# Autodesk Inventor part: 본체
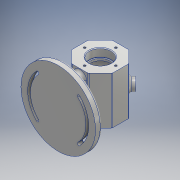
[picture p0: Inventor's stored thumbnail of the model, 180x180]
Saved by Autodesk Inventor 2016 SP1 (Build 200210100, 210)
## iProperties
Created: 2017-06
Part Number: 본체
Material: 알루미늄 6061
Document SubType Name: Modeling
Designer: basic
Density: 2.7 g/cm^3
Appearance: 알루미늄 - 평지
Mass: 554.247 g
Surface Area: 559.738 cm^2
Volume: 205.277 cm^3
Author: basic
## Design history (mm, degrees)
sketch "스케치1"
  geometry: L1 (0, 0)-(30.406, 30.406); L2 (0, 0)-(72.458, 0); L3 (0, 0)-(-65.505, 0); L4 (-30.406, 30.406)-(0, 0); C1 r 55 at (0, 0); A1 r 43 centre (0, 0) between (30.406, -30.406) and (30.406, 30.406); A2 r 48 centre (0, 0) between (33.941, -33.941) and (33.941, 33.941); A3 r 38 centre (0, 0) between (26.87, -26.87) and (26.87, 26.87); A4 r 5 centre (30.406, -30.406) between (26.87, -26.87) and (33.941, -33.941); A5 r 5 centre (30.406, 30.406) between (33.941, 33.941) and (26.87, 26.87); A6 r 43 centre (0, 0) between (-30.406, 30.406) and (-30.406, -30.406); A7 r 48 centre (0, 0) between (-33.941, 33.941) and (-33.941, -33.941); A8 r 38 centre (0, 0) between (-26.87, 26.87) and (-26.87, -26.87); A9 r 5 centre (-30.406, 30.406) between (-26.87, 26.87) and (-33.941, 33.941); A10 r 5 centre (-30.406, -30.406) between (-33.941, -33.941) and (-26.87, -26.87); 3 further points
  constraints: 22 point on circle, 11 centre point, 8 end point, 8 tangent, 3 coincident, 2 horizontal, 2 horizontal alignment
  dimensions: "d0" = 110 diameter of C1; "d1" = 48 radius of A2; "d2" = 48 radius of A7; "d3" = 38 radius of A3; "d4" = 38 radius of A8; "d9" = 45 deg angle of L2 L1; "d10" = 45 deg angle of L3 L4
extrude "돌출1" new body sketch "스케치1" distance "d11" = 10; taper "d12" = 0 deg
sketch "스케치2"
  geometry: L1 (30, 49.574)-(12.426, 32); L2 (12.426, 32)-(-12.426, 32); L3 (-12.426, 32)-(-30, 49.574); L4 (-30, 49.574)-(-30, 74.426); L5 (-30, 74.426)-(-12.426, 92); L6 (-12.426, 92)-(12.426, 92); L7 (12.426, 92)-(30, 74.426); L8 (30, 74.426)-(30, 49.574); L9 (-38, 0)-(-38, 10) reference; L10 (-38, 10)-(38, 10) reference; L11 (38, 10)-(38, 0) reference; L12 (38, 0)-(-38, 0) reference; L13 (55, 10)-(55, 0) reference; L14 (55, 0)-(48, 0) reference; L15 (48, 0)-(48, 10) reference; L16 (48, 10)-(55, 10) reference; L17 (-55, 0)-(-55, 10) reference; L18 (-55, 10)-(-48, 10) reference; L19 (-48, 10)-(-48, 0) reference; L20 (-48, 0)-(-55, 0) reference; C1 r 30 at (0, 62); 2 further points
  constraints: 16 end point, 1 centre point, 1 coincident, 1 parallel, 1 tangent, 1 vertical alignment, 17 other
  dimensions: "d13" = 62 distance from line of L12 point (0, 62); "d14" = 60 diameter of C1
extrude "돌출2" join sketch "스케치2" stored distance "d15" = 70; taper "d16" = 0 deg
sketch "스케치4"
  geometry: L1 (-30, 74.426)-(-30, 49.574) reference; C1 r 16 at (0, 62); 2 further points
  constraints: 1 centre point, 1 horizontal alignment, 1 midpoint, 1 vertical alignment
  dimensions: "d20" = 32 diameter of C1
extrude "돌출3" cut sketch "스케치4" distance "d21" = 12; taper "d22" = 0 deg
sketch "스케치5"
  geometry: L1 (-30, 12.426)-(-30, -12.426) reference; L2 (-12.426, -30)-(12.426, -30) reference; C1 r 14 at (0, 0); 4 further points
  constraints: 3 midpoint, 1 centre point, 1 horizontal alignment, 1 vertical alignment
  dimensions: "d24" = 28 diameter of C1
extrude "돌출4" cut sketch "스케치5" distance "d25" = 3; taper "d26" = 0 deg
sketch "스케치6"
  geometry: L1 (-12.426, 32)-(12.426, 32) reference; L2 (-30, 74.426)-(-30, 49.574) reference; C1 r 16 at (0, 62); 3 further points
  constraints: 2 midpoint, 1 centre point, 1 horizontal alignment, 1 vertical alignment
  dimensions: "d27" = 32 diameter of C1
extrude "돌출5" cut sketch "스케치6" distance "d28" = 12; taper "d29" = 0 deg
sketch "스케치7"
  geometry: L1 (-30, 12.426)-(-30, -12.426) reference; C1 r 14 at (0, 0); 2 further points
  constraints: 1 centre point, 1 horizontal alignment, 1 midpoint, 1 vertical alignment
  dimensions: "d30" = 28 diameter of C1
extrude "돌출6" cut sketch "스케치7" distance "d31" = 3; taper "d32" = 0 deg
node "작업 평면1"
sketch "스케치8"
  geometry: L1 (-38, 0)-(-38, 10) reference; L2 (-38, 10)-(38, 10) reference; L3 (38, 10)-(38, 0) reference; L4 (38, 0)-(-38, 0) reference; L5 (55, 10)-(55, 0) reference; L6 (55, 0)-(48, 0) reference; L7 (48, 0)-(48, 10) reference; L8 (48, 10)-(55, 10) reference; L9 (-55, 0)-(-55, 10) reference; L10 (-55, 10)-(-48, 10) reference; L11 (-48, 10)-(-48, 0) reference; L12 (-48, 0)-(-55, 0) reference; L13 (12.426, 32)-(-12.426, 32) reference; L14 (-12.426, 32)-(-30, 49.574) reference; L15 (-30, 49.574)-(-30, 74.426) reference; L16 (-30, 74.426)-(-12.426, 92) reference; L17 (-12.426, 92)-(12.426, 92) reference; L18 (12.426, 92)-(30, 74.426) reference; L19 (30, 74.426)-(30, 49.574) reference; L20 (30, 49.574)-(12.426, 32) reference; C1 r 25 at (0, 62); 3 further points
  constraints: 2 midpoint, 1 centre point, 1 horizontal alignment, 1 vertical alignment
  dimensions: "d33" = 50 diameter of C1
extrude "돌출7" cut sketch "스케치8" stored distance "d34" = 40; taper "d35" = 0 deg
sketch "스케치9"
  geometry: L1 (0, -24)-(0, 24); L2 (5, -24)-(5, 24); L3 (-5, 24)-(-5, -24); A1 r 5 centre (0, -24) between (-5, -24) and (5, -24); A2 r 5 centre (0, 24) between (5, 24) and (-5, 24); 1 further point
  constraints: 8 end point, 4 point on circle, 4 tangent, 2 centre point, 1 midpoint, 1 parallel, 1 vertical
  dimensions: "d36" = 48 distance of L1.start L1.end; "d37" = 5 radius of A1
extrude "돌출8" join sketch "스케치9" stored distance "d38" = 40; taper "d39" = 0 deg
sketch "스케치10"
  geometry: L1 (-24.853, 70)-(0, 70) reference; C1 r 8 at (-12.426, 35); 2 further points
  constraints: 1 centre point, 1 horizontal alignment, 1 midpoint, 1 vertical alignment
  dimensions: "d40" = 16 diameter of C1
extrude "돌출9" join sketch "스케치10" distance "d41" = 7; taper "d42" = 0 deg
hole "구멍1" diameter "d45" = 8; stored, may be unused: countersink angle "d49" = 90 deg, drill point angle "d51" = 118 deg; dims "d43" = 10, "d44" = 10, "d46" = 6, "d47" = 4, "d48" = 2, "d50" = 8
sketch "스케치11"
  geometry: L1 (-42.426, 10)-(-32.378, 10) reference; L2 (-32.378, 10)-(-32.378, 0) reference; L3 (-32.378, 0)-(-42.426, 0) reference; L4 (-42.426, 0)-(-42.426, 10) reference; L5 (-28.433, 10)-(28.433, 10) reference; L6 (28.433, 10)-(28.433, 0) reference; L7 (28.433, 0)-(-28.433, 0) reference; L8 (-28.433, 0)-(-28.433, 10) reference; L9 (32.378, 10)-(42.426, 10) reference; L10 (42.426, 10)-(42.426, 0) reference; L11 (42.426, 0)-(32.378, 0) reference; L12 (32.378, 0)-(32.378, 10) reference; L13 (-12.426, 92)-(12.426, 92) reference; L14 (12.426, 92)-(30, 74.426) reference; L15 (30, 74.426)-(30, 49.574) reference; L16 (30, 49.574)-(12.426, 32) reference; L17 (12.426, 32)-(-12.426, 32) reference; L18 (-12.426, 32)-(-30, 49.574) reference; L19 (-30, 49.574)-(-30, 74.426) reference; L20 (-30, 74.426)-(-12.426, 92) reference; C1 r 16 at (0, 62) reference; 2 further points
  constraints: 1 vertical alignment
  dimensions: "d52" = 23 distance of C1.centre point (0, 85)
hole "구멍2" sketch "스케치11" at (0, 85) diameter "d53" = 3.242; stored, may be unused: countersink angle "d57" = 90 deg, drill point angle "d59" = 118 deg; dims "d54" = 8, "d55" = 4, "d56" = 2, "d58" = 10
fillet "모깎기1" dims "d63" = 0.3
fillet "모깎기2" dims "d64" = 3
chamfer "모따기1" distance "d65" = 1; stored, may be unused: second distance "d66" = 2, angle "d67" = 45 deg
chamfer "모따기2" distance "d68" = 1; stored, may be unused: second distance "d69" = 2, angle "d70" = 45 deg
fillet "모깎기3" dims "d71" = 5
sketch "스케치13"
  geometry: C1 r 55 at (0, 0) reference; A1 r 5 centre (30.406, 30.406) between (33.941, 33.941) and (26.87, 26.87) reference; A2 r 38 centre (0, 0) between (26.87, -26.87) and (26.87, 26.87) reference; A3 r 5 centre (30.406, -30.406) between (26.87, -26.87) and (33.941, -33.941) reference; A4 r 48 centre (0, 0) between (33.941, -33.941) and (33.941, 33.941) reference; A5 r 5 centre (-30.406, -30.406) between (-33.941, -33.941) and (-26.87, -26.87) reference; A6 r 38 centre (0, 0) between (-26.87, 26.87) and (-26.87, -26.87) reference; A7 r 5 centre (-30.406, 30.406) between (-26.87, 26.87) and (-33.941, 33.941) reference; A8 r 48 centre (0, 0) between (-33.941, 33.941) and (-33.941, -33.941) reference; A9 r 2 centre (30.406, 30.406) between (31.82, 31.82) and (28.991, 28.991); A10 r 45 centre (0, 0) between (31.82, -31.82) and (31.82, 31.82); A11 r 2 centre (30.406, -30.406) between (28.991, -28.991) and (31.82, -31.82); A12 r 41 centre (0, 0) between (28.991, -28.991) and (28.991, 28.991); A13 r 2 centre (-30.406, -30.406) between (-31.82, -31.82) and (-28.991, -28.991); A14 r 45 centre (0, 0) between (-31.82, 31.82) and (-31.82, -31.82); A15 r 2 centre (-30.406, 30.406) between (-28.991, 28.991) and (-31.82, 31.82); A16 r 41 centre (0, 0) between (-28.991, 28.991) and (-28.991, -28.991); 1 further point
  constraints: 16 point on circle, 8 centre point, 6 other
  dimensions: "d88" = 2 radius of A13; "d89" = 2 radius of A9
  node "절단 모서리 투영6"
extrude "돌출10" join sketch "스케치13" distance "d75" = 7; taper "d76" = 0 deg
extrude "돌출11" join sketch "스케치13" distance "d77" = 7; taper "d78" = 0 deg
fillet "모깎기4" dims "d79" = 3
fillet "모깎기5" dims "d80" = 3
chamfer "모따기3" distance "d81" = 1; stored, may be unused: second distance "d82" = 2, angle "d83" = 45 deg
sketch "스케치14"
  geometry: L1 (22.853, 0)-(0, 0) reference; L2 (-18.574, 70)-(-18.574, 0) reference; 2 further points
  constraints: 1 other
  dimensions: "d84" = 35 distance from line of L1 point (11.426, 35); "d85" = 30 distance from line of L2 point (11.426, 35)
feature "엠보싱1" sketch "스케치14" dims "d86" = 0.5, "d87" = 0
node "솔리드1"
pattern_circular "원형 패턴1" dims angle "d61" = 360 deg
mirror "대칭1"
node "절단 모서리 투영1"
node "절단 모서리 투영3"
node "절단 모서리 투영4"
